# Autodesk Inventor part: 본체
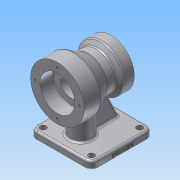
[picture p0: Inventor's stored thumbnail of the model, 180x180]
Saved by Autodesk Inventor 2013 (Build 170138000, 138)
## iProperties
Created: 2019-01
Part Number: 본체
Material: 알루미늄 6061
Document SubType Name: Modeling
Designer: Administrator
Density: 2.71 g/cm^3
Mass: 902.547 g
Surface Area: 602.628 cm^2
Volume: 333.043 cm^3
Author: Administrator
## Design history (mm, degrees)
sketch "스케치1"
  geometry: L1 (-46, -46)-(-46, 46); L2 (-46, 46)-(46, 46); L3 (46, 46)-(46, -46); L4 (46, -46)-(-46, -46); L5 (-46, -46)-(46, 46); L6 (-46, 46)-(46, -46); 1 further point
  constraints: 12 end point, 2 midpoint, 2 parallel, 2 perpendicular, 1 horizontal
  dimensions: "d0" = 92 distance of L1.end L2.end
extrude "돌출1" new body sketch "스케치1" distance "d2" = 10; taper "d3" = 0 deg
fillet "모깎기1" dims "d8" = 10
sketch "스케치3"
  geometry: C1 r 4.5 at (-36, 36); A1 r 10 centre (-36, 36) between (-36, 46) and (-46, 36) reference; 1 further point
  constraints: 1 centre point, 1 coincident
  dimensions: "d9" = 9 diameter of C1
extrude "돌출2" cut sketch "스케치3" stored distance "d11" = 10; taper "d12" = 0 deg
sketch "스케치5"
  geometry: L1 (-46, 36)-(-46, -36) reference; L2 (36, 46)-(-36, 46) reference; C1 r 16 at (-16, 0); 1 further point
  constraints: 1 centre point
  dimensions: "d19" = 46 distance from line of L2 C1.centre; "d20" = 30 distance from line of C1.centre L1; "d22" = 16 radius of C1
sketch "스케치7"
  geometry: L1 (51, 80)-(-29, 80); L2 (-36, 0)-(36, 0) reference; L3 (36, 10)-(-36, 10) reference; L4 (51, 120)-(26, 120); L5 (5.215, 108)-(-8.126, 108); L6 (-8.126, 108)-(-14, 115); L7 (-14, 115)-(-29, 115); L8 (-29, 115)-(-29, 100); L9 (-29, 100)-(-12, 100); L10 (-12, 100)-(-12, 96); L11 (-12, 96)-(31, 96); L12 (31, 96)-(31, 106); L13 (31, 106)-(51, 106); L14 (51, 106)-(51, 120); L15 (5.215, 108)-(26, 120); L16 (46, 10)-(46, 0) reference; 2 further points
  constraints: 26 end point, 8 parallel, 2 vertical alignment, 1 horizontal, 1 midpoint, 1 perpendicular, 1 vertical
  dimensions: "d23" = 80 distance between parallel lines of L2 L1; "d24" = 80 distance of L1.start L1.end; "d25" = 25 distance of L4.start L4.end; "d26" = 15 distance of L6.end L7.end; "d27" = 20 distance of L12.end L13.end; "d28" = 17 distance of L8.end L9.end; "d30" = 40 diameter of L9 L1; "d31" = 32 diameter of L11 L1; "d32" = 52 diameter of L13 L1; "d33" = 80 diameter of L4 L1; "d34" = 70 diameter of L7 L1; "d37" = 50 deg angle of L5 L6; "d38" = 30 deg angle of L5 L15; "d39" = 56 diameter of L5 L1; "d44" = 5 distance from line of L16 L1.start
revolve "회전1" sketch "스케치7" stored, may be unused: angle "d40" = 90 deg
extrude "돌출3" join sketch "스케치5" stored distance "d41" = 10; taper "d42" = 0 deg
sketch "스케치11"
  geometry: L1 (-36, -46)-(36, -46) reference; L2 (46, -36)-(46, 36) reference; L3 (36, -5)-(-0.801, -5); L4 (-0.801, -5)-(-0.801, 5); L5 (-0.801, 5)-(36, 5); L6 (36, 5)-(36, -5); L7 (36, -5)-(-0.801, 5); L8 (-0.801, -5)-(36, 5); A1 r 16 centre (-16, 0) between (0, 0) and (-0.801, 5) reference; 2 further points
  constraints: 12 end point, 3 midpoint, 3 parallel, 1 horizontal alignment, 1 perpendicular, 1 point on circle
  dimensions: "d51" = 10 distance between parallel lines of L2 L6; "d52" = 10 distance of L5.end L3.start
extrude "돌출4" join sketch "스케치11" stored distance "d53" = 10; taper "d54" = 0 deg
feature "면 기울기1" dims angle "d55" = 25 deg
fillet "모깎기2" dims "d56" = 0.6
fillet "모깎기3" dims "d57" = 1
fillet "모깎기4" dims "d58" = 3
fillet "모깎기5" dims "d59" = 3
fillet "모깎기6" dims "d60" = 3
fillet "모깎기7" dims "d61" = 3
sketch "스케치12" dims "d63" = 66
  geometry: L1 (-80, -36)-(-80, 36) reference; C1 r 40 at (0, 0) reference; 4 further points
  constraints: 2 horizontal alignment, 1 coincident, 1 midpoint, 2 other
hole "구멍1" sketch "스케치12" at (33, 0) diameter "d65" = 3.242; stored, may be unused: countersink angle "d69" = 90 deg, drill point angle "d71" = 118 deg; dims "d66" = 9, "d67" = 4, "d68" = 2, "d70" = 11
sketch "스케치13" dims "d75" = 55
  geometry: C1 r 35 at (0, 0) reference; C2 r 20 at (0, 0) reference; 3 further points
  constraints: 2 horizontal alignment, 1 coincident, 2 other
hole "구멍2" sketch "스케치13" at (27.5, 0) diameter "d77" = 3.242; stored, may be unused: countersink angle "d81" = 90 deg, drill point angle "d83" = 118 deg; dims "d78" = 9, "d79" = 4, "d80" = 2, "d82" = 11
fillet "모깎기8" dims "d87" = 3
sketch "스케치14"
  geometry: L1 (72, 0)-(0, 0) reference; L2 (-10, 7)-(-10, 0) reference; 2 further points
  constraints: 1 other
  dimensions: "d88" = 46 distance from line of point (36, 4) L2; "d89" = 4 distance from line of L1 point (36, 4)
feature "엠보싱1" sketch "스케치14" dims "d0" = 92, "d16" = 20, "d90" = 0.5, "d91" = 0
node "솔리드1"
pattern_linear "직사각형 패턴1" dims "d15" = 72, "d18" = 72
pattern_circular "원형 패턴1" dims angle "d73" = 360 deg
pattern_circular "원형 패턴2" dims angle "d85" = 360 deg
